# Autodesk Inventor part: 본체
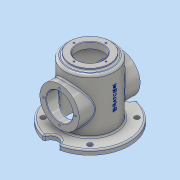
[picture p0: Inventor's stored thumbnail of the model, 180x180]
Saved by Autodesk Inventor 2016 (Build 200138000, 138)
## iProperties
Created: 2018-04
Part Number: 본체
Material: 알루미늄 6061
Document SubType Name: Modeling
Designer: 605-11
Density: 2.7 g/cm^3
Appearance: 알루미늄 - 평지
Mass: 1149.88 g
Surface Area: 1203.14 cm^2
Volume: 425.883 cm^3
Author: 605-11
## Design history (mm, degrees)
sketch "스케치1"
  geometry: C1 r 80 at (0, 0); 1 further point
  constraints: 1 centre point, 1 coincident
  dimensions: "d0" = 160 diameter of C1
extrude "돌출1" new body sketch "스케치1" distance "d1" = 10; taper "d2" = 0 deg
sketch "스케치2"
  geometry: C1 r 50 at (0, 0); 1 further point
  constraints: 1 centre point, 1 coincident
  dimensions: "d3" = 100 diameter of C1
extrude "돌출2" join sketch "스케치2" distance "d4" = 110; taper "d5" = 0 deg
sketch "스케치3"
  geometry: C1 r 40 at (0, 0); 1 further point
  constraints: 1 centre point, 1 coincident
  dimensions: "d6" = 80 diameter of C1
extrude "돌출3" join sketch "스케치3" distance "d7" = 5; taper "d8" = 0 deg
sketch "스케치4"
  geometry: C1 r 50 at (0, 0); 1 further point
  constraints: 1 centre point, 1 coincident
  dimensions: "d9" = 100 diameter of C1
extrude "돌출4" join sketch "스케치4" distance "d10" = 8; taper "d11" = 0 deg
sketch "스케치5"
  geometry: L1 (-8, 50)-(-8, -50) reference; L2 (0, 80)-(0, -80) reference; C1 r 40 at (60, 0); 1 further point
  constraints: 1 centre point, 1 horizontal alignment
  dimensions: "d12" = 80 diameter of C1; "d77" = 60 distance from line of L2 C1.centre
extrude "돌출5" join sketch "스케치5" stored distance "d14" = 124; taper "d15" = 0 deg
sketch "스케치6"
  geometry: L1 (-50, -68)-(50, -68) reference; C1 r 40 at (0, 0) reference; C2 r 27 at (0, 0); 2 further points
  constraints: 1 centre point, 1 coincident, 1 midpoint
  dimensions: "d17" = 54 diameter of C2
extrude "돌출6" cut sketch "스케치6" stored distance "d18" = 124; taper "d19" = 0 deg
sketch "스케치7"
  geometry: C1 r 27 at (0, 0); 1 further point
  constraints: 1 centre point, 1 coincident
  dimensions: "d20" = 54 diameter of C1
extrude "돌출7" cut sketch "스케치7" stored distance "d21" = 124; taper "d22" = 0 deg
sketch "스케치8"
  geometry: C1 r 45 at (0, 0); 1 further point
  constraints: 1 centre point, 1 coincident
  dimensions: "d23" = 90 diameter of C1
extrude "돌출8" cut sketch "스케치8" distance "d24" = 120; taper "d25" = 0 deg
sketch "스케치9"
  geometry: L1 (-94.935, 0)-(94.935, 0); C1 r 15 at (-80, 0); C2 r 15 at (80, 0); A1 r 80 centre (0, 0) between (-80, 0) and (80, 0) reference; 2 further points
  constraints: 2 centre point, 2 coincident, 2 end point, 2 point on circle, 2 point on line, 1 horizontal, 1 midpoint
  dimensions: "d28" = 30 diameter of C1; "d29" = 30 diameter of C2
extrude "돌출9" cut sketch "스케치9" distance "d30" = 120; taper "d31" = 0 deg
sketch "스케치10" dims "d33" = 135
  geometry: L1 (0, 0)-(0, 146.955); L2 (0, 0)-(-87.168, 87.168); 2 further points
  constraints: 4 end point, 1 coincident, 1 point on line, 1 vertical, 3 other
  dimensions: "d32" = 45 deg angle of L1 L2
hole "구멍1" sketch "스케치10" at (-47.73, 47.73) diameter "d34" = 10; stored, may be unused: countersink angle "d38" = 90 deg, drill point angle "d40" = 118 deg; dims "d35" = 6, "d36" = 4, "d37" = 2, "d39" = 8
sketch "스케치11" dims "d44" = 65
  geometry: L1 (0, 0)-(0, 111.67); 2 further points
  constraints: 2 end point, 1 coincident, 1 point on line, 1 vertical, 1 vertical alignment, 2 other
hole "구멍2" sketch "스케치11" at (0, 32.5) diameter "d45" = 3.242; stored, may be unused: countersink angle "d49" = 90 deg, drill point angle "d51" = 118 deg; dims "d46" = 8, "d47" = 4, "d48" = 2, "d50" = 10
sketch "스케치12" dims "d55" = 65
  geometry: L1 (0, 0)-(0, 55.862); C1 r 27 at (0, 0) reference; 3 further points
  constraints: 2 end point, 1 coincident, 1 point on line, 1 vertical, 1 vertical alignment, 2 other
hole "구멍3" sketch "스케치12" at (0, 32.5) diameter "d56" = 3.242; stored, may be unused: countersink angle "d60" = 90 deg, drill point angle "d62" = 118 deg; dims "d57" = 8, "d58" = 4, "d59" = 2, "d61" = 10
node "작업 평면1"
sketch "스케치13"
  geometry: L1 (-3, 50)-(-3, 70); L2 (-3, 70)-(3, 70); L3 (3, 70)-(3, 50); L4 (3, 50)-(-3, 50); L5 (-78.594, -10)-(78.594, -10) reference; L6 (-50, -18)-(50, -18) reference; 3 further points
  constraints: 2 midpoint, 1 vertical alignment, 2 other
  dimensions: "d66" = 6 distance of L1.end L2.end; "d67" = 20 distance of L1.start L1.end; "d82" = 60 distance between parallel lines of L4 L5
feature "엠보싱1" sketch "스케치13" dims "d69" = 0.5, "d70" = 0
fillet "모깎기1" dims "d71" = 3
fillet "모깎기2" dims "d72" = 3
fillet "모깎기3" dims "d73" = 3
fillet "모깎기5" dims "d75" = 3
fillet "모깎기6" dims "d76" = 3
fillet "모깎기7" dims "d78" = 3
chamfer "모따기1" distance "d79" = 1; stored, may be unused: second distance "d80" = 2, angle "d81" = 45 deg
fillet "모깎기8" dims "d83" = 5
fillet "모깎기9" dims "d84" = 3
node "솔리드1"
pattern_circular "원형 패턴1" dims angle "d42" = 360 deg
pattern_circular "원형 패턴2" dims angle "d53" = 360 deg
pattern_circular "원형 패턴3" dims angle "d64" = 360 deg
mirror "대칭1"
node "투영된 루프1"
